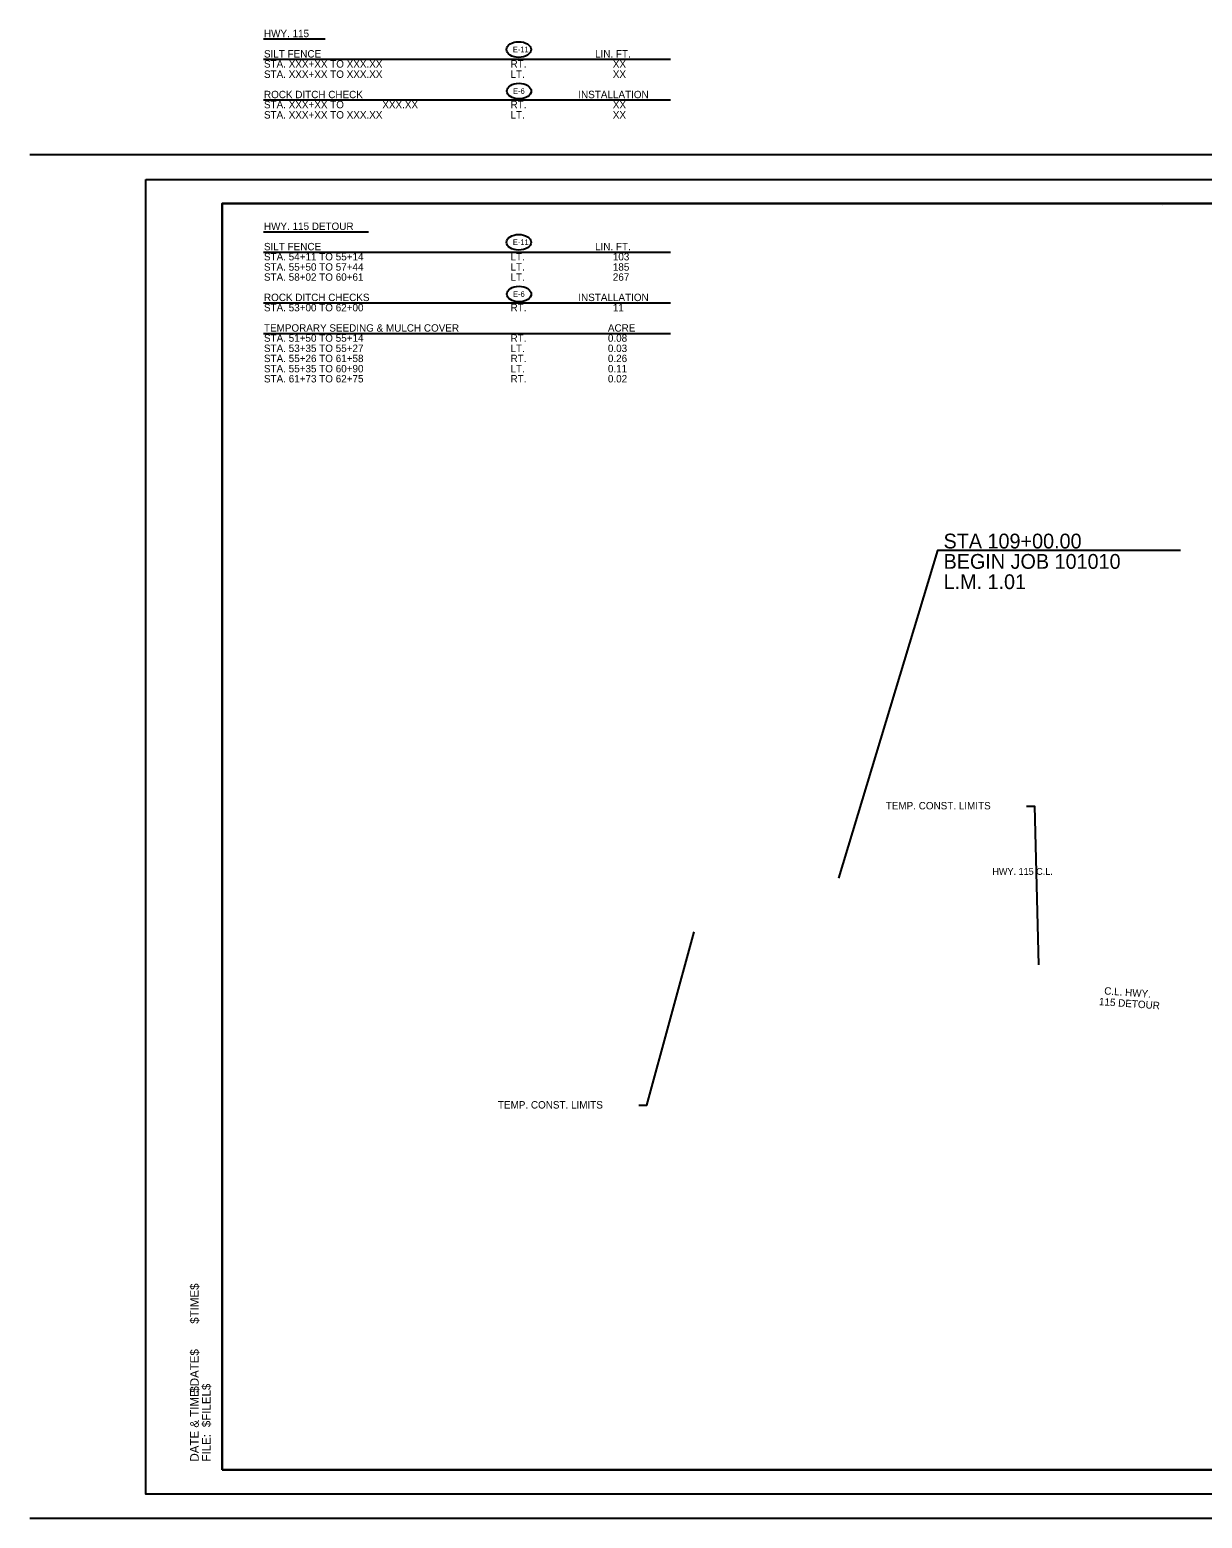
# Model space of a CAD drawing. Extents: x 7675 to 14104, y 9961 to 11168.
# Drawn here: x 9844 to 10795, y 9961 to 11168 of the extents above; entities that cross this region are included whole.
import ezdxf

# ---------------------------------------------------------------- set-up
doc = ezdxf.new("R2010")
doc.units = 0
for name, color, linetype in [('GREEN_TXT', 7, 'Continuous'), ('S_TREE', 7, 'Continuous'), ('SEAL-INFO', 7, 'Continuous'), ('Stage 1 Construction', 7, 'Continuous'), ('Stage 1 Ditch Checks', 7, 'Continuous'), ('Stage 2 Construction', 7, 'Continuous'), ('Stage 2 Flow Arrows', 7, 'Continuous')]:
    doc.layers.add(name, color=color, linetype=linetype)

msp = doc.modelspace()

# ---------------------------------------------------------------- linework, layer by layer
at = {"layer": 'GREEN_TXT'}
for p, q in [((11603.9, 11066.7), (9843.9, 11066.7)), ((10000, 11027.3), (11580.9, 11027.3)), ((10000, 10000), (10000, 11027.3)), ((10762.6, 11026), (10762.6, 11026)), ((10762.6, 11026), (10762.6, 11026)), ((11580.9, 10000), (10000, 10000)), ((9843.9, 9960.6), (11603.9, 9960.6))]:
    msp.add_line(p, q, dxfattribs=at)
at = {"layer": 'SEAL-INFO'}
msp.add_lwpolyline([(9938, 11046.8), (11604.7, 11046.8), (11604.7, 9980.1), (9938, 9980.1)], close=True, dxfattribs=at)
at = {"layer": 'Stage 1 Construction'}
msp.add_lwpolyline([(10777.4, 10745.8), (10580.4, 10745.8), (10500, 10480)], dxfattribs=at)
at = {"layer": 'Stage 1 Ditch Checks'}
msp.add_lwpolyline([(10000, 10000), (11580.9, 10000), (11580.3, 10963.3), (11365.4, 10963.3), (11357.3, 10959.9), (11348.5, 10961.4), (11348.3, 10977.9), (11169.6, 10977.9), (11169.6, 11027.3), (10000, 11027.3)], close=True, dxfattribs=at)
at = {"layer": 'Stage 2 Construction'}
for points in [[(10652.4, 10538.4), (10659.1, 10538.4), (10662.3, 10409.6)], [(10337.9, 10295.7), (10344.6, 10295.7), (10382.9, 10436.4)]]:
    msp.add_lwpolyline(points, dxfattribs=at)
at = {"layer": 'Stage 2 Flow Arrows'}
for p, q in [((10033.6, 11160.8), (10083.6, 11160.8)), ((10033.6, 11144.3), (10363.6, 11144.3)), ((10033.6, 11111.3), (10363.6, 11111.3)), ((10033.6, 11004.4), (10118.6, 11004.4)), ((10033.6, 10987.9), (10363.6, 10987.9)), ((10033.6, 10946.6), (10363.6, 10946.6)), ((10033.6, 10921.9), (10363.6, 10921.9))]:
    msp.add_line(p, q, dxfattribs=at)
for centre in [(10240.6, 11152.2), (10240.8, 11118.5), (10240.6, 10995.8), (10240.8, 10953.8)]:
    msp.add_ellipse(centre, major_axis=(9.94, 0), ratio=0.638788, dxfattribs=at)

# ---------------------------------------------------------------- texts
for s, height, p in [('$TIME$', 6.98, (9981, 10118.4)), ('$DATE$', 6.98, (9981, 10062.5)), ('DATE & TIME:', 6.984, (9981, 10006.6)), ('$FILEL$', 6.98, (9990.6, 10034.5)), ('FILE: ', 6.98, (9990.6, 10006.6))]:
    msp.add_text(s, height=height, rotation=90).set_placement(p)
at = {"layer": 'S_TREE'}
msp.add_text('HWY. 115 C.L.', height=5.5, dxfattribs=at).set_placement((10624.8, 10482.6))
for s, p in [('C.L. HWY.', (10715.4, 10385.6)), ('115 DETOUR', (10711.1, 10376.9))]:
    msp.add_text(s, height=6, rotation=356.0356, dxfattribs=at).set_placement(p)
at = {"layer": 'Stage 1 Construction'}
for s, p in [('STA 109+00.00', (10585.2, 10747.4)), ('BEGIN JOB 101010', (10585.2, 10730.9)), ('L.M. 1.01', (10585.2, 10714.4))]:
    msp.add_text(s, height=12, dxfattribs=at).set_placement(p)
at = {"layer": 'Stage 2 Construction'}
for p in [(10538.3, 10535.7), (10223.7, 10293)]:
    msp.add_text('TEMP. CONST. LIMITS', height=6, dxfattribs=at).set_placement(p)
at = {"layer": 'Stage 2 Flow Arrows'}
for s, height, p in [('HWY. 115', 6, (10033.9, 11162.2)), ('SILT FENCE', 6, (10033.9, 11145.7)), ('E-11', 4.54, (10235.8, 11150)), ('LIN. FT.', 6, (10302.5, 11145.7)), ('STA. XXX+XX TO XXX.XX', 6, (10033.9, 11137.5)), ('STA. XXX+XX TO XXX.XX', 6, (10033.9, 11129.2)), ('RT.', 6, (10233.9, 11137.5)), ('LT.', 6, (10233.9, 11129.2)), ('XX', 6, (10316.9, 11137.5)), ('XX', 6, (10316.9, 11129.2)), ('STA. XXX+XX TO', 6, (10033.9, 11104.5)), ('ROCK DITCH CHECK', 6, (10033.9, 11112.7)), ('XXX.XX', 6, (10129.9, 11104.5)), ('RT.', 6, (10233.9, 11104.5)), ('INSTALLATION', 6, (10288.9, 11112.7)), ('XX', 6, (10316.9, 11104.5)), ('STA. XXX+XX TO XXX.XX', 6, (10033.9, 11096.2)), ('LT.', 6, (10233.9, 11096.2)), ('XX', 6, (10316.9, 11096.2)), ('HWY. 115 DETOUR', 6, (10033.9, 11005.8)), ('SILT FENCE', 6, (10033.9, 10989.3)), ('E-11', 4.54, (10235.8, 10993.6)), ('LIN. FT.', 6, (10302.5, 10989.3)), ('STA. 54+11 TO 55+14', 6, (10033.9, 10981.1)), ('STA. 55+50 TO 57+44', 6, (10033.9, 10972.8)), ('LT.', 6, (10233.9, 10981.1)), ('LT.', 6, (10233.9, 10972.8)), ('103', 6, (10316.9, 10981.1)), ('185', 6, (10316.9, 10972.8)), ('STA. 58+02 TO 60+61', 6, (10033.9, 10964.6)), ('LT.', 6, (10233.9, 10964.6)), ('267', 6, (10316.9, 10964.6)), ('ROCK DITCH CHECKS', 6, (10033.9, 10948.1)), ('INSTALLATION', 6, (10288.9, 10948.1)), ('STA. 53+00 TO 62+00', 6, (10033.9, 10939.8)), ('RT.', 6, (10233.9, 10939.8)), ('11', 6, (10316.9, 10939.8)), ('TEMPORARY SEEDING & MULCH COVER', 6, (10033.9, 10923.3)), ('ACRE', 6, (10312.9, 10923.3)), ('STA. 51+50 TO 55+14', 6, (10033.9, 10915.1)), ('RT.', 6, (10233.9, 10915.1)), ('0.08', 6, (10312.9, 10915.1)), ('STA. 53+35 TO 55+27', 6, (10033.9, 10906.8)), ('LT.', 6, (10233.9, 10906.8)), ('0.03', 6, (10312.9, 10906.8)), ('STA. 55+26 TO 61+58', 6, (10033.9, 10898.6)), ('STA. 55+35 TO 60+90', 6, (10033.9, 10890.3)), ('RT.', 6, (10233.9, 10898.6)), ('LT.', 6, (10233.9, 10890.3)), ('0.26', 6, (10312.9, 10898.6)), ('0.11', 6, (10312.9, 10890.3)), ('STA. 61+73 TO 62+75', 6, (10033.9, 10882.1)), ('RT.', 6, (10233.9, 10882.1)), ('0.02', 6, (10312.9, 10882.1))]:
    msp.add_text(s, height=height, dxfattribs=at).set_placement(p)
for p in [(10236, 11116.2), (10236, 10951.5)]:
    msp.add_text('E-6', height=4.54, rotation=360, dxfattribs=at).set_placement(p)

doc.saveas('drawing.dxf')
